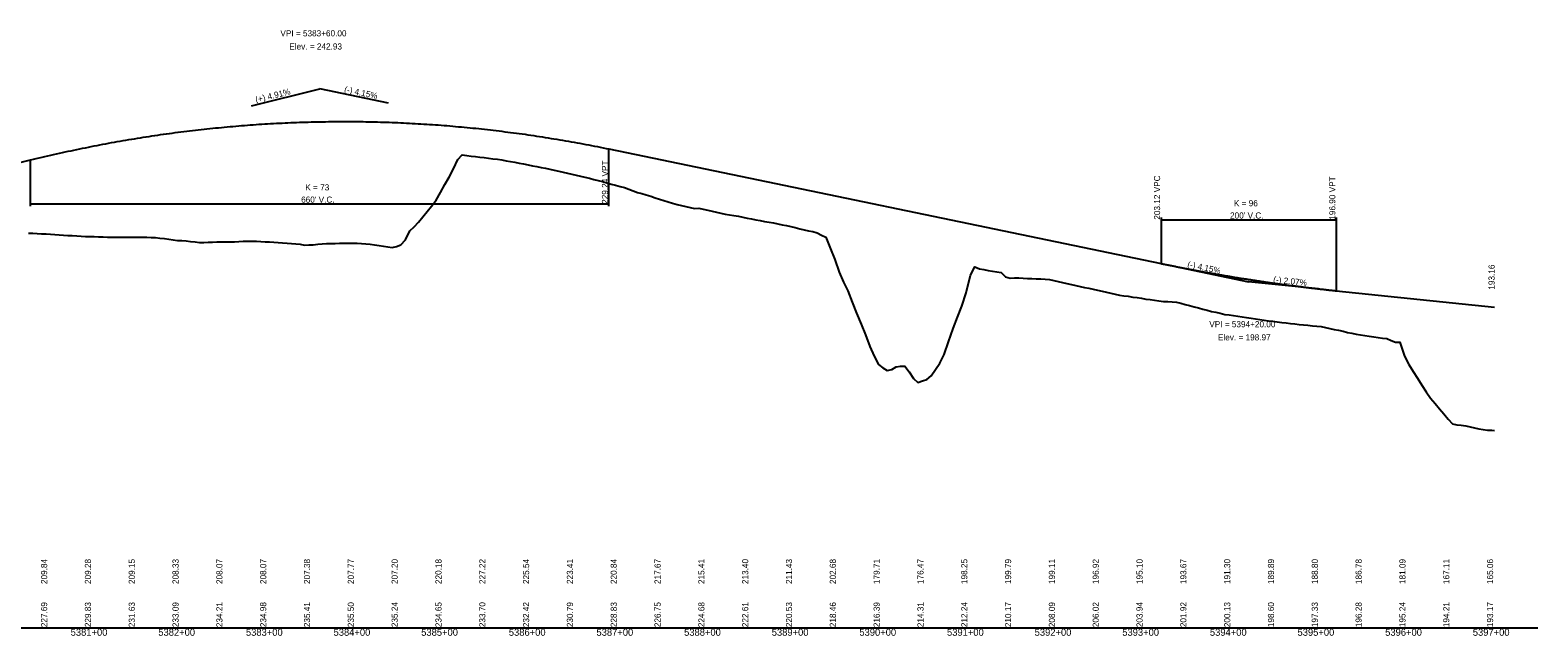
# Model space of a CAD drawing. Extents: x 1876258 to 1932803, y 754739 to 837911.
# Drawn here: x 1878161 to 1879882, y 773480 to 774171 of the extents above; entities that cross this region are included whole.
import ezdxf

# ---------------------------------------------------------------- set-up
doc = ezdxf.new("R2010")
doc.units = 0
for name, color, linetype in [('RD_DDB_GradeTX', 7, 'Continuous'), ('RD_DDB_Profile_EX', 7, 'Continuous'), ('RD_DDB_Profile_Lbl', 7, 'Continuous'), ('RD_DDB_Profile_PR', 7, 'Continuous'), ('RD_DDB_StaTX', 7, 'Continuous'), ('RD_DDB_StripGrade', 7, 'Continuous'), ('RD_DDB_VCLbl', 7, 'Continuous'), ('RD_GPK_Profile_Cell', 7, 'Continuous')]:
    doc.layers.add(name, color=color, linetype=linetype)

msp = doc.modelspace()

# ---------------------------------------------------------------- linework, layer by layer
at = {"layer": 'RD_DDB_GradeTX'}
for p, q in [((1878413.9, 774084.7), (1878491.6, 774103.8)), ((1878570, 774087.5), (1878491.6, 774103.8)), ((1879473.3, 773900.2), (1879551.6, 773884)), ((1879631.2, 773875.7), (1879551.6, 773884))]:
    msp.add_line(p, q, dxfattribs=at)
at = {"layer": 'RD_DDB_Profile_EX'}
for points in [[(1878184.3, 773938.2), (1878189.3, 773937.9), (1878194.3, 773937.6), (1878199.3, 773937.2), (1878204.3, 773936.8), (1878209.3, 773936.5), (1878214.3, 773936.2), (1878219.3, 773936), (1878224.3, 773935.7), (1878229.3, 773935.6), (1878234.3, 773935.5), (1878239.3, 773935.3), (1878244.3, 773935.1), (1878249.3, 773934.9), (1878254.3, 773934.8), (1878259.3, 773934.8), (1878264.3, 773934.7), (1878269.3, 773934.8), (1878274.3, 773934.8), (1878279.3, 773934.9), (1878284.3, 773934.9), (1878289.3, 773934.8), (1878294.3, 773934.9), (1878299.3, 773934.5), (1878304.3, 773934.2), (1878309.3, 773933.7), (1878314.3, 773933.2), (1878319.3, 773932.6), (1878324.3, 773931.6), (1878329.3, 773930.8), (1878334.3, 773930.8), (1878339.3, 773930.5), (1878344.3, 773929.9), (1878349.3, 773929.3), (1878354.3, 773928.8), (1878359.3, 773928.7), (1878364.3, 773928.9), (1878369.3, 773929.2), (1878374.3, 773929.5), (1878379.3, 773929.5), (1878384.3, 773929.5), (1878389.3, 773929.5), (1878394.3, 773929.6), (1878399.3, 773930), (1878404.3, 773930.3), (1878409.3, 773930.2), (1878414.3, 773930.2), (1878419.3, 773930.2), (1878424.3, 773930), (1878429.3, 773929.6), (1878434.3, 773929.3), (1878439.3, 773929), (1878444.3, 773928.7), (1878449.3, 773928.2), (1878454.3, 773928), (1878459.3, 773927.6), (1878464.3, 773927.3), (1878469.3, 773926.7), (1878474.3, 773925.7), (1878479.3, 773925.9), (1878484.3, 773926.2), (1878489.3, 773926.8), (1878494.3, 773927.3), (1878499.3, 773927.4), (1878504.3, 773927.5), (1878509.3, 773927.6), (1878514.3, 773927.8), (1878519.3, 773927.9), (1878524.3, 773928), (1878529.3, 773928), (1878534.3, 773927.9), (1878539.3, 773927.5), (1878544.3, 773927), (1878549.3, 773926.6), (1878554.3, 773926.1), (1878559.3, 773925.3), (1878564.3, 773924.6), (1878569.3, 773923.8), (1878574.3, 773923.1), (1878579.3, 773924.3), (1878584.3, 773926.1), (1878589.3, 773931.7), (1878594.3, 773941.9), (1878599.3, 773946.4), (1878604.3, 773951.7), (1878609.3, 773957.9), (1878614.3, 773964), (1878619.3, 773970.3), (1878624.3, 773977.1), (1878629.3, 773985.9), (1878634.3, 773994.9), (1878639.3, 774003.3), (1878644.3, 774012.8), (1878649.3, 774023.3), (1878654.3, 774028.5), (1878659.3, 774027.8), (1878664.3, 774027.2), (1878669.3, 774026.7), (1878674.3, 774026.2), (1878679.3, 774025.6), (1878684.3, 774024.9)], [(1878684.3, 774024.9), (1878689.3, 774024.3), (1878694.3, 774023.6), (1878699.3, 774022.9), (1878704.3, 774022), (1878709.3, 774021.1), (1878714.3, 774020.2), (1878719.3, 774019.3), (1878724.3, 774018.3), (1878729.3, 774017.3), (1878734.3, 774016.3), (1878739.3, 774015.4), (1878744.3, 774014.4), (1878749.3, 774013.4), (1878754.3, 774012.4), (1878759.3, 774011.3), (1878764.3, 774010.1), (1878769.3, 774009), (1878774.3, 774007.9), (1878779.3, 774006.7), (1878784.3, 774005.6), (1878789.3, 774004.4), (1878794.3, 774003.3), (1878799.3, 774002), (1878804.3, 774000.6), (1878809.3, 773999.4), (1878814.3, 773998.1), (1878819.3, 773996.7), (1878824.3, 773995.3), (1878829.3, 773994), (1878834.3, 773992.6), (1878839.3, 773991.5), (1878844.3, 773989.7), (1878849.3, 773987.7), (1878854.3, 773985.6), (1878859.3, 773984.6), (1878864.3, 773983.1), (1878869.3, 773981.4), (1878874.3, 773979.8), (1878879.3, 773978.2), (1878884.3, 773976.6), (1878889.3, 773975), (1878894.3, 773973.5), (1878899.3, 773971.9), (1878904.3, 773970.7), (1878909.3, 773969.7), (1878914.3, 773968.7), (1878919.3, 773967.5), (1878924.3, 773967.7), (1878929.3, 773966.6), (1878934.3, 773965.7), (1878939.3, 773964.5), (1878944.3, 773963.2), (1878949.3, 773962), (1878954.3, 773961.1), (1878959.3, 773960.1), (1878964.3, 773959.3), (1878969.3, 773958.6), (1878974.3, 773957.7), (1878979.3, 773956.6), (1878984.3, 773955.6), (1878989.3, 773954.6), (1878994.3, 773953.6), (1878999.3, 773952.7), (1879004.3, 773952), (1879009.3, 773951.1), (1879014.3, 773950.1), (1879019.3, 773949), (1879024.3, 773948), (1879029.3, 773946.9), (1879034.3, 773945.7), (1879039.3, 773944.2), (1879044.3, 773943.1), (1879049.3, 773942.1), (1879054.3, 773941.1), (1879059.3, 773939.9), (1879064.3, 773937.2), (1879069.3, 773934.8), (1879074.3, 773921.6), (1879079.3, 773909.3), (1879084.3, 773894.7), (1879089.3, 773883.5), (1879094.3, 773873.4), (1879099.3, 773860.8), (1879104.3, 773848.1), (1879109.3, 773835.7), (1879114.3, 773823.5), (1879119.3, 773810.2), (1879124.3, 773798.9), (1879129.3, 773789.4), (1879134.3, 773785.8), (1879139.3, 773782.7), (1879144.3, 773784), (1879149.3, 773786.7), (1879154.3, 773787.8), (1879159.3, 773787.7), (1879164.3, 773781.2), (1879169.3, 773773.6), (1879174.3, 773769.1), (1879179.3, 773770.8), (1879184.3, 773772.3)], [(1878159.3, 773939.5), (1878164.3, 773939.2), (1878169.3, 773938.9), (1878174.3, 773938.7), (1878179.3, 773938.5), (1878184.3, 773938.2)], [(1879184.3, 773772.3), (1879189.3, 773776.7), (1879194.3, 773783.9), (1879199.3, 773791), (1879204.3, 773800.8), (1879209.3, 773815.4), (1879214.3, 773830.6), (1879219.3, 773843.6), (1879224.3, 773855.9), (1879229.3, 773871.1), (1879234.3, 773891.3), (1879239.3, 773901), (1879244.3, 773898.6), (1879249.3, 773897.7), (1879254.3, 773896.9), (1879259.3, 773896.1), (1879264.3, 773895.3), (1879269.3, 773894.6), (1879274.3, 773889.7), (1879279.3, 773888), (1879284.3, 773888.2), (1879289.3, 773888.2), (1879294.3, 773888), (1879299.3, 773887.7), (1879304.3, 773887.5), (1879309.3, 773887.3), (1879314.3, 773887.1), (1879319.3, 773886.9), (1879324.3, 773886.3), (1879329.3, 773885.2), (1879334.3, 773884.1), (1879339.3, 773883), (1879344.3, 773881.9), (1879349.3, 773880.8), (1879354.3, 773879.6), (1879359.3, 773878.5), (1879364.3, 773877.5), (1879369.3, 773876.5), (1879374.3, 773875.5), (1879379.3, 773874.3), (1879384.3, 773873.2), (1879389.3, 773872), (1879394.3, 773870.9), (1879399.3, 773869.8), (1879404.3, 773868.8), (1879409.3, 773868), (1879414.3, 773867.3), (1879419.3, 773866.5), (1879424.3, 773865.8), (1879429.3, 773865), (1879434.3, 773864.2), (1879439.3, 773863.5), (1879444.3, 773862.8), (1879449.3, 773862), (1879454.3, 773861.3), (1879459.3, 773861.4), (1879464.3, 773860.9), (1879469.3, 773860.5), (1879474.3, 773859.4), (1879479.3, 773858.1), (1879484.3, 773856.8), (1879489.3, 773855.4), (1879494.3, 773854.1), (1879499.3, 773852.8), (1879504.3, 773851.4), (1879509.3, 773850.1), (1879514.3, 773849.2), (1879519.3, 773847.9), (1879524.3, 773846.7), (1879529.3, 773846), (1879534.3, 773845.3), (1879539.3, 773844.5), (1879544.3, 773843.8), (1879549.3, 773843.1), (1879554.3, 773842.3), (1879559.3, 773841.6), (1879564.3, 773840.9), (1879569.3, 773840.1), (1879574.3, 773839.5), (1879579.3, 773838.9), (1879584.3, 773838.2), (1879589.3, 773837.6), (1879594.3, 773837), (1879599.3, 773836.4), (1879604.3, 773835.8), (1879609.3, 773835.2), (1879614.3, 773834.8), (1879619.3, 773834.3), (1879624.3, 773833.8), (1879629.3, 773833.4), (1879634.3, 773832.8), (1879639.3, 773831.7), (1879644.3, 773830.7), (1879649.3, 773829.6), (1879654.3, 773828.5), (1879659.3, 773827.4), (1879664.3, 773826.1), (1879669.3, 773825.2), (1879674.3, 773824.3), (1879679.3, 773823.4), (1879684.3, 773822.5)], [(1879684.3, 773822.5), (1879689.3, 773821.7), (1879694.3, 773820.9), (1879699.3, 773820.2), (1879704.3, 773819.5), (1879709.3, 773819.1), (1879714.3, 773817), (1879719.3, 773815.1), (1879724.3, 773814.9), (1879729.3, 773799), (1879734.3, 773789.5), (1879739.3, 773781.7), (1879744.3, 773773.8), (1879749.3, 773766), (1879754.3, 773758.2), (1879759.3, 773751.3), (1879764.3, 773745.2), (1879769.3, 773739), (1879774.3, 773733.4), (1879779.3, 773727), (1879784.3, 773722), (1879789.3, 773720.8), (1879794.3, 773720.3), (1879799.3, 773719.4), (1879804.3, 773718.3), (1879809.3, 773717.3), (1879814.3, 773716.3), (1879819.3, 773715.3), (1879824.3, 773714.8), (1879829.3, 773714.6), (1879832.3, 773714.4)]]:
    msp.add_lwpolyline(points, dxfattribs=at)
at = {"layer": 'RD_DDB_Profile_PR'}
for p, q in [((1878821.6, 774035.4), (1879451.6, 773904.7)), ((1878071.6, 774000.7), (1878161.6, 774022.8)), ((1879651.6, 773873.6), (1879832.3, 773854.9))]:
    msp.add_line(p, q, dxfattribs=at)
for points in [[(1878161.6, 774022.8), (1878174.8, 774026), (1878188, 774029), (1878201.2, 774032), (1878214.4, 774034.8), (1878227.6, 774037.5), (1878240.8, 774040.1), (1878254, 774042.6), (1878267.2, 774044.9), (1878280.4, 774047.1), (1878293.6, 774049.2), (1878306.8, 774051.2), (1878320, 774053.1), (1878333.2, 774054.8), (1878346.4, 774056.4), (1878359.6, 774057.9), (1878372.8, 774059.3), (1878386, 774060.6), (1878399.2, 774061.7), (1878412.4, 774062.8), (1878425.6, 774063.7), (1878438.8, 774064.5), (1878452, 774065.1), (1878465.2, 774065.7), (1878478.4, 774066.1), (1878491.6, 774066.4), (1878504.8, 774066.6), (1878518, 774066.7), (1878531.2, 774066.6), (1878544.4, 774066.5), (1878557.6, 774066.2), (1878570.8, 774065.8), (1878584, 774065.3), (1878597.2, 774064.6), (1878610.4, 774063.8), (1878623.6, 774063), (1878636.8, 774062), (1878650, 774060.8), (1878663.2, 774059.6), (1878676.4, 774058.2), (1878689.6, 774056.7), (1878702.8, 774055.1), (1878716, 774053.4), (1878729.2, 774051.6), (1878742.4, 774049.6), (1878755.6, 774047.5), (1878768.8, 774045.3), (1878782, 774043), (1878795.2, 774040.6), (1878808.4, 774038), (1878821.6, 774035.4)], [(1879451.6, 773904.7), (1879455.6, 773903.9), (1879459.6, 773903.1), (1879463.6, 773902.3), (1879467.6, 773901.5), (1879471.6, 773900.7), (1879475.6, 773899.9), (1879479.6, 773899.1), (1879483.6, 773898.3), (1879487.6, 773897.6), (1879491.6, 773896.8), (1879495.6, 773896.1), (1879499.6, 773895.4), (1879503.6, 773894.6), (1879507.6, 773893.9), (1879511.6, 773893.2), (1879515.6, 773892.5), (1879519.6, 773891.8), (1879523.6, 773891.1), (1879527.6, 773890.5), (1879531.6, 773889.8), (1879535.6, 773889.1), (1879539.6, 773888.5), (1879543.6, 773887.8), (1879547.6, 773887.2), (1879551.6, 773886.6), (1879555.6, 773886), (1879559.6, 773885.4), (1879563.6, 773884.8), (1879567.6, 773884.2), (1879571.6, 773883.6), (1879575.6, 773883), (1879579.6, 773882.4), (1879583.6, 773881.9), (1879587.6, 773881.3), (1879591.6, 773880.8), (1879595.6, 773880.2), (1879599.6, 773879.7), (1879603.6, 773879.2), (1879607.6, 773878.7), (1879611.6, 773878.2), (1879615.6, 773877.7), (1879619.6, 773877.2), (1879623.6, 773876.7), (1879627.6, 773876.3), (1879631.6, 773875.8), (1879635.6, 773875.4), (1879639.6, 773874.9), (1879643.6, 773874.5), (1879647.6, 773874.1), (1879651.6, 773873.6)]]:
    msp.add_spline(points, degree=3, dxfattribs=at)
at = {"layer": 'RD_DDB_VCLbl'}
for p, q in [((1878821.6, 773970.3), (1878821.6, 774035.4)), ((1878161.6, 773970.3), (1878161.6, 774022.8)), ((1878161.6, 773972.8), (1878821.6, 773972.8)), ((1879451.6, 773957.2), (1879451.6, 773904.7)), ((1879451.6, 773954.7), (1879651.6, 773954.7)), ((1879651.6, 773957.2), (1879651.6, 773873.6))]:
    msp.add_line(p, q, dxfattribs=at)
at = {"layer": 'RD_GPK_Profile_Cell'}
msp.add_line((1877681.6, 773489.1), (1879881.6, 773489.1), dxfattribs=at)

# ---------------------------------------------------------------- texts
at = {"layer": 'RD_DDB_GradeTX'}
for s, rotation, p in [('(+) 4.91%', 13.7861, (1878419, 774088)), ('(-) 4.15%', 348.2855, (1878519.1, 774100.1)), ('(-) 4.15%', 348.2855, (1879481.2, 773900.6)), ('(-) 2.07%', 354.0927, (1879579.4, 773883.1))]:
    msp.add_text(s, height=7, rotation=rotation, dxfattribs=at).set_placement(p)
at = {"layer": 'RD_DDB_Profile_Lbl'}
for s, p in [('VPI = 5383+60.00', (1878446.7, 774163.8)), ('Elev. = 242.93', (1878456.9, 774148.8)), ('VPI = 5394+20.00', (1879506.7, 773832)), ('Elev. = 198.97', (1879516.6, 773817))]:
    msp.add_text(s, height=7, dxfattribs=at).set_placement(p)
msp.add_text('193.16', height=7, rotation=90, dxfattribs=at).set_placement((1879832.3, 773874.9))
at = {"layer": 'RD_DDB_StaTX'}
for s, p in [('5381+00', (1878207.4, 773480.1)), ('5382+00', (1878307.4, 773480.1)), ('5383+00', (1878407.4, 773480.1)), ('5384+00', (1878507.4, 773480.1)), ('5385+00', (1878607.4, 773480.1)), ('5386+00', (1878707.4, 773480.1)), ('5387+00', (1878807.4, 773480.1)), ('5388+00', (1878907.4, 773480.1)), ('5389+00', (1879007.4, 773480.1)), ('5390+00', (1879107.4, 773480.1)), ('5391+00', (1879207.4, 773480.1)), ('5392+00', (1879307.4, 773480.1)), ('5393+00', (1879407.4, 773480.1)), ('5394+00', (1879507.4, 773480.1)), ('5395+00', (1879607.4, 773480.1)), ('5396+00', (1879707.4, 773480.1)), ('5397+00', (1879807.4, 773480.1))]:
    msp.add_text(s, height=8, dxfattribs=at).set_placement(p)
at = {"layer": 'RD_DDB_StripGrade'}
for s, p in [('229.24 VPT', (1878820.6, 773972.8)), ('203.12 VPC', (1879450.6, 773954.7)), ('196.90 VPT', (1879650.6, 773954.7)), ('209.84', (1878180.6, 773539.1)), ('209.28', (1878230.6, 773539.1)), ('209.15', (1878280.6, 773539.1)), ('208.33', (1878330.6, 773539.1)), ('208.07', (1878380.6, 773539.1)), ('208.07', (1878430.6, 773539.1)), ('207.38', (1878480.6, 773539.1)), ('207.77', (1878530.6, 773539.1)), ('207.20', (1878580.6, 773539.1)), ('220.18', (1878630.6, 773539.1)), ('227.22', (1878680.6, 773539.1)), ('225.54', (1878730.6, 773539.1)), ('223.41', (1878780.6, 773539.1)), ('220.84', (1878830.6, 773539.1)), ('217.67', (1878880.6, 773539.1)), ('215.41', (1878930.6, 773539.1)), ('213.40', (1878980.6, 773539.1)), ('211.43', (1879030.6, 773539.1)), ('202.68', (1879080.6, 773539.1)), ('179.71', (1879130.6, 773539.1)), ('176.47', (1879180.6, 773539.1)), ('198.25', (1879230.6, 773539.1)), ('199.79', (1879280.6, 773539.1)), ('199.11', (1879330.6, 773539.1)), ('196.92', (1879380.6, 773539.1)), ('195.10', (1879430.6, 773539.1)), ('193.67', (1879480.6, 773539.1)), ('191.30', (1879530.6, 773539.1)), ('189.89', (1879580.6, 773539.1)), ('188.80', (1879630.6, 773539.1)), ('186.78', (1879680.6, 773539.1)), ('181.09', (1879730.6, 773539.1)), ('167.11', (1879780.6, 773539.1)), ('165.06', (1879830.6, 773539.1)), ('227.69', (1878180.6, 773489.9)), ('229.83', (1878230.6, 773489.9)), ('231.63', (1878280.6, 773489.9)), ('233.09', (1878330.6, 773489.9)), ('234.21', (1878380.6, 773489.9)), ('234.98', (1878430.6, 773489.9)), ('235.41', (1878480.6, 773489.9)), ('235.50', (1878530.6, 773489.9)), ('235.24', (1878580.6, 773489.9)), ('234.65', (1878630.6, 773489.9)), ('233.70', (1878680.6, 773489.9)), ('232.42', (1878730.6, 773489.9)), ('230.79', (1878780.6, 773489.9)), ('228.83', (1878830.6, 773489.9)), ('226.75', (1878880.6, 773489.9)), ('224.68', (1878930.6, 773489.9)), ('222.61', (1878980.6, 773489.9)), ('220.53', (1879030.6, 773489.9)), ('218.46', (1879080.6, 773489.9)), ('216.39', (1879130.6, 773489.9)), ('214.31', (1879180.6, 773489.9)), ('212.24', (1879230.6, 773489.9)), ('210.17', (1879280.6, 773489.9)), ('208.09', (1879330.6, 773489.9)), ('206.02', (1879380.6, 773489.9)), ('203.94', (1879430.6, 773489.9)), ('201.92', (1879480.6, 773489.9)), ('200.13', (1879530.6, 773489.9)), ('198.60', (1879580.6, 773489.9)), ('197.33', (1879630.6, 773489.9)), ('196.28', (1879680.6, 773489.9)), ('195.24', (1879730.6, 773489.9)), ('194.21', (1879780.6, 773489.9)), ('193.17', (1879830.6, 773489.9))]:
    msp.add_text(s, height=7, rotation=90, dxfattribs=at).set_placement(p)
at = {"layer": 'RD_DDB_VCLbl'}
for s, p in [("660' V.C.", (1878470.4, 773974.1)), ('K = 73', (1878475.2, 773988.1)), ("200' V.C.", (1879530.4, 773956)), ('K = 96', (1879534.8, 773970))]:
    msp.add_text(s, height=7, dxfattribs=at).set_placement(p)

doc.saveas('drawing.dxf')
